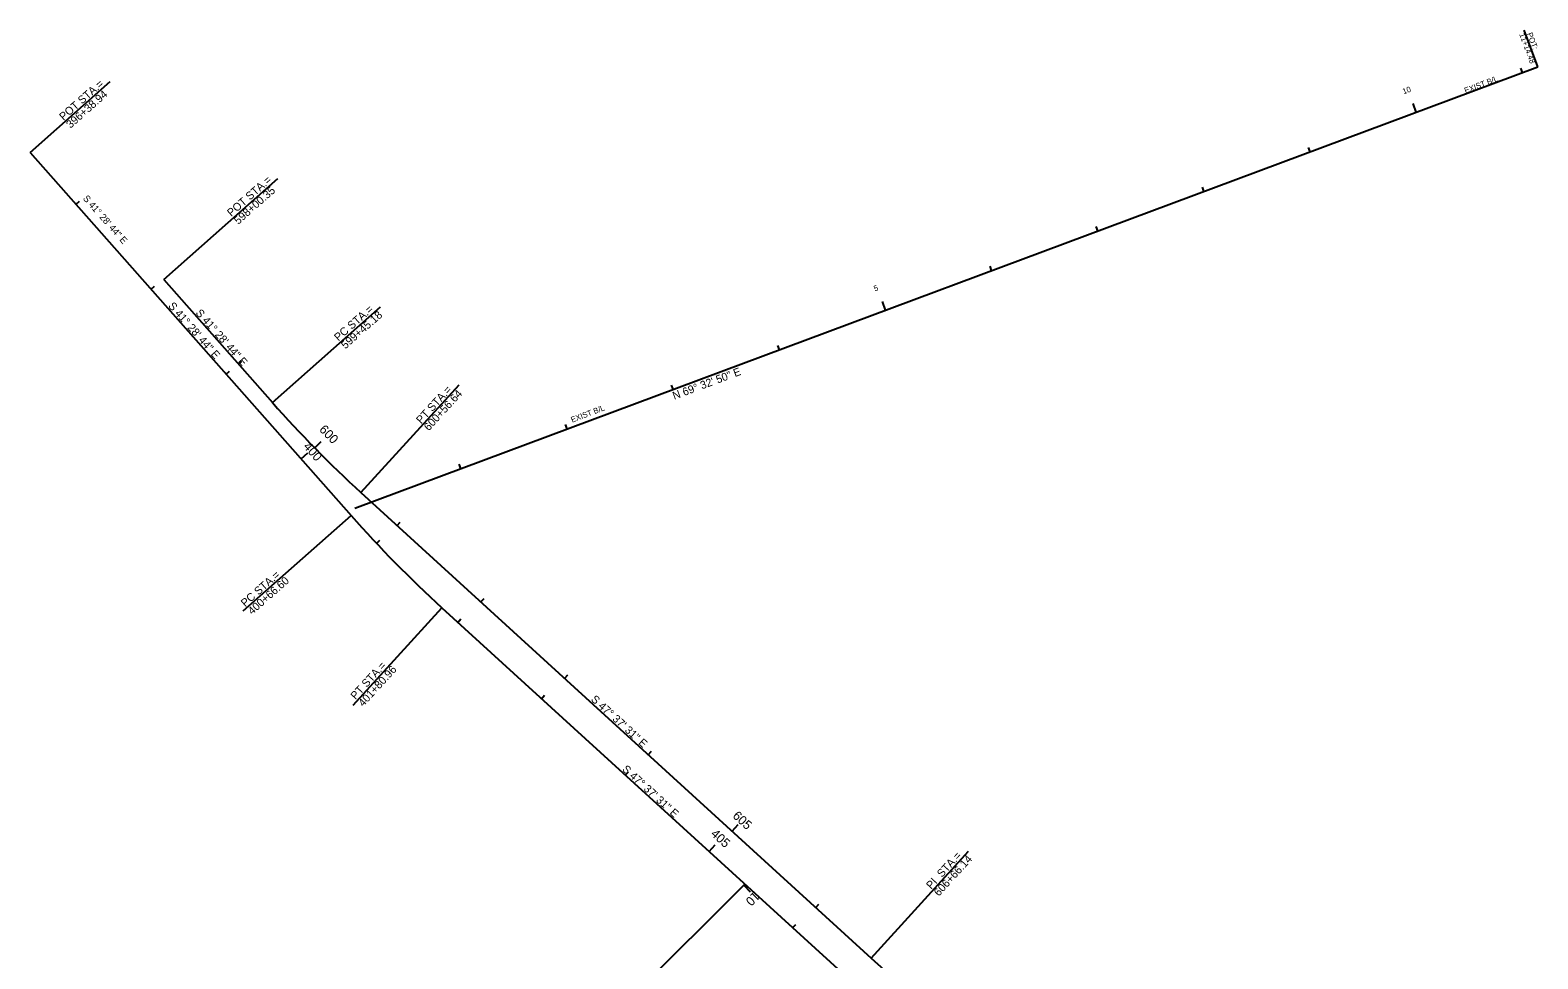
# Model space of a CAD drawing. Extents: x 1944333 to 1978554, y 788952 to 827675.
# Drawn here: x 1970303 to 1971633, y 803186 to 804005 of the extents above; entities that cross this region are included whole.
import ezdxf

# ---------------------------------------------------------------- set-up
doc = ezdxf.new("R2010")
doc.units = 0
for name, color, linetype in [('RD_HC_Cl', 7, 'Continuous'), ('RD_HC_CL_Rel', 7, 'Continuous'), ('RD_HC_Data', 7, 'Continuous'), ('RD_HC_Data_Rel', 7, 'Continuous'), ('RD_HC_Data_Tic', 7, 'Continuous'), ('RD_HC_Data_Tic_Rel', 7, 'Continuous'), ('RD_HC_Survey_txCode', 7, 'Continuous'), ('RD_HC_TX_Rel_Sta50', 7, 'Continuous')]:
    doc.layers.add(name, color=color, linetype=linetype)

msp = doc.modelspace()

# ---------------------------------------------------------------- linework, layer by layer
at = {"layer": 'RD_HC_Cl'}
msp.add_line((1970589, 803583.4), (1971633.2, 803972.9), dxfattribs=at)
at = {"layer": 'RD_HC_CL_Rel'}
for p, q in [((1970302.5, 803897.3), (1970585.8, 803576.9)), ((1970420.4, 803785.1), (1970516.3, 803676.6)), ((1970594.5, 803597.2), (1971044.7, 803186.4)), ((1970666, 803495.5), (1971028.6, 803164.7)), ((1970933.3, 803251.6), (1970790.6, 803109.5)), ((1971044.7, 803186.4), (1971437.2, 802836))]:
    msp.add_line(p, q, dxfattribs=at)
for centre, radius in [((1971294.7, 804364.8), 1039), ((1971384.4, 804283), 1066)]:
    msp.add_arc(centre, radius, 221.479, 227.6252, dxfattribs=at)
at = {"layer": 'RD_HC_Data_Rel'}
for p, q in [((1971633.2, 803972.9), (1971621.1, 804005.2)), ((1970302.5, 803897.3), (1970373.2, 803959.8)), ((1970420.4, 803785.1), (1970521.1, 803874.2)), ((1970516.3, 803676.6), (1970611.7, 803760.9)), ((1970594.5, 803597.2), (1970681.2, 803692.3)), ((1970490.6, 803492.8), (1970585.8, 803576.9)), ((1970587.6, 803409.6), (1970666, 803495.5)), ((1971044.7, 803186.4), (1971130.6, 803280.6))]:
    msp.add_line(p, q, dxfattribs=at)
at = {"layer": 'RD_HC_Data_Tic'}
for p, q in [((1971619.6, 803967.8), (1971618.2, 803971.6)), ((1971525.9, 803932.9), (1971523.1, 803940.4)), ((1971432.2, 803897.9), (1971430.8, 803901.7)), ((1971338.5, 803863), (1971337.1, 803866.7)), ((1971244.8, 803828), (1971243.4, 803831.8)), ((1971151.1, 803793.1), (1971149.7, 803796.8)), ((1971057.4, 803758.2), (1971054.7, 803765.7)), ((1970963.8, 803723.2), (1970962.4, 803727)), ((1970870.1, 803688.3), (1970868.7, 803692)), ((1970776.4, 803653.3), (1970775, 803657.1)), ((1970682.7, 803618.4), (1970681.3, 803622.1))]:
    msp.add_line(p, q, dxfattribs=at)
at = {"layer": 'RD_HC_Data_Tic_Rel'}
for p, q in [((1970343, 803851.6), (1970346, 803854.2)), ((1970409.2, 803776.6), (1970412.2, 803779.3)), ((1970486.4, 803710.5), (1970489.4, 803713.1)), ((1970475.4, 803701.7), (1970478.4, 803704.4)), ((1970541.7, 803626.8), (1970547.7, 803632.1)), ((1970553.7, 803636.5), (1970559.4, 803642.1)), ((1970626.5, 803568), (1970629.2, 803571)), ((1970608.3, 803552.2), (1970611.2, 803555)), ((1970700.4, 803500.6), (1970703.1, 803503.6)), ((1970680, 803482.6), (1970682.7, 803485.6)), ((1970774.3, 803433.2), (1970777, 803436.2)), ((1970753.9, 803415.2), (1970756.6, 803418.2)), ((1970848.1, 803365.8), (1970850.8, 803368.8)), ((1970827.8, 803347.8), (1970830.5, 803350.8)), ((1970922, 803298.4), (1970927.4, 803304.3)), ((1970901.7, 803280.4), (1970907.1, 803286.3)), ((1970932.3, 803250.6), (1970938, 803244.9)), ((1970995.9, 803231), (1970998.6, 803234)), ((1970975.5, 803213), (1970978.2, 803216))]:
    msp.add_line(p, q, dxfattribs=at)

# ---------------------------------------------------------------- texts
at = {"layer": 'RD_HC_Data'}
msp.add_text('N 69%%d 32\' 50" E', height=7, rotation=20.4528, dxfattribs=at).set_placement((1970871, 803679))
at = {"layer": 'RD_HC_Data_Rel'}
for s, height, rotation, p in [('11+14.48', 5, 290.4528, (1971616.7, 804001.5)), (' POT:', 5, 290.4528, (1971622.8, 804003.8)), ('POT STA.=', 7, 41.479, (1970332, 803925)), ('396+38.94', 7, 41.479, (1970338.1, 803918.1)), ('10', 5, 20.4528, (1971514.8, 803948.5)), ('POT STA.=', 7, 41.479, (1970480.1, 803840.2)), ('S 41%%d 28\' 44" E', 6, 311.479, (1970348.7, 803856.4)), ('598+00.35', 7, 41.479, (1970486.2, 803833.3)), ('5', 5, 20.4528, (1971048.1, 803774.5)), ('S 41%%d 28\' 44" E', 7, 311.479, (1970423.9, 803761.5)), ('S 41%%d 28\' 44" E', 7, 311.479, (1970448.1, 803755.3)), ('PC STA.=', 7, 41.479, (1970574.6, 803730.3)), ('599+45.18', 7, 41.479, (1970580.7, 803723.4)), ('PT STA.=', 7, 47.6252, (1970647.6, 803657.3)), ('600+56.64', 7, 47.6252, (1970654.4, 803651.1)), ('PC STA.=', 7, 41.479, (1970492.3, 803495.8)), ('400+66.60', 7, 41.479, (1970498.4, 803488.9)), ('PT STA.=', 7, 47.6252, (1970589.7, 803413.9)), ('401+80.96', 7, 47.6252, (1970596.5, 803407.7)), ('S 47%%d 37\' 31" E', 7, 317.6252, (1970796.9, 803413.9)), ('S 47%%d 37\' 31" E', 7, 317.6252, (1970824.5, 803352.2)), ('PI  STA.=', 7, 47.6252, (1971097.8, 803246.6)), ('606+66.14', 7, 47.6252, (1971104.5, 803240.4))]:
    msp.add_text(s, height=height, rotation=rotation, dxfattribs=at).set_placement(p)
at = {"layer": 'RD_HC_Survey_txCode'}
for p in [(1971569.4, 803949.3), (1970780.9, 803658.8)]:
    msp.add_text('EXIST B/L', height=5, rotation=20.8269, dxfattribs=at).set_placement(p)
at = {"layer": 'RD_HC_TX_Rel_Sta50'}
for s, rotation, p in [('600', 314.5019, (1970557.1, 803652.2)), ('400', 311.479, (1970543.1, 803637.4)), ('605', 317.6252, (1970921.9, 803311)), ('405', 317.6252, (1970902.7, 803295.1)), ('10', 224.8665, (1970941.8, 803245.7))]:
    msp.add_text(s, height=8, rotation=rotation, dxfattribs=at).set_placement(p)

doc.saveas('drawing.dxf')
